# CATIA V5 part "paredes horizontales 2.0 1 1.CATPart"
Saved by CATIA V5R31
Part number: paredes horizontales 2.0
Bounding box of the stored display mesh (mm): x -153.3 to 153.3, y 0 to 3.3, z 0 to 315
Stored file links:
  C:\Users\189361\Desktop\paredes horizontales 2.0 1 1.CATPart
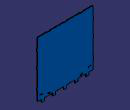
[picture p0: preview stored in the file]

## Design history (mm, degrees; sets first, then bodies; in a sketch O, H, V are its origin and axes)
Body1 (main body)
  Sketch1 on zx-plane, origin (0, 0, 0), H (-1, 0, 0), V (0, 0, 1)
    point P1 (-127.65, 15)
    line L1 (-127.65, 15) -> (-150, 15)
    point P2 (-150, 15)
    line L2 (-150, 15) -> (-150, 65)
    point P3 (-150, 65)
    line L3 (-150, 65) -> (-153.3, 65)
    point P4 (-153.3, 65)
    line L4 (-153.3, 65) -> (-153.3, 80)
    point P5 (-153.3, 80)
    line L5 (-153.3, 80) -> (-150, 80)
    point P6 (-150, 80)
    line L6 (-150, 80) -> (-150, 165)
    point P7 (-150, 165)
    line L7 (-150, 165) -> (-153.3, 165)
    point P8 (-153.3, 165)
    line L8 (-153.3, 165) -> (-153.3, 180)
    point P9 (-153.3, 180)
    line L9 (-153.3, 180) -> (-150, 180)
    point P10 (-150, 180)
    line L10 (-150, 180) -> (-150, 247.5)
    point P11 (-150, 247.5)
    line L11 (-150, 247.5) -> (-153.3, 247.5)
    point P12 (-153.3, 247.5)
    line L12 (-153.3, 247.5) -> (-153.3, 262.5)
    point P13 (-150, 315)
    line L13 (-150, 315) -> (-97.5, 315)
    point P14 (-97.5, 315)
    line L14 (-97.5, 315) -> (-97.5, 311.7)
    point P15 (-97.5, 311.7)
    line L15 (-97.5, 311.7) -> (-82.5, 311.7)
    point P16 (-82.5, 311.7)
    line L16 (-82.5, 311.7) -> (-82.5, 315)
    point P17 (-82.5, 315)
    line L17 (-82.5, 315) -> (-7.5, 315)
    point P18 (-7.5, 315)
    line L18 (-7.5, 315) -> (-7.5, 311.7)
    point P19 (-7.5, 311.7)
    line L19 (-7.5, 311.7) -> (0, 311.7)
    point P20 (0, 311.7)
    line L20 (-127.65, 15) -> (-127.65, 0)
    point P21 (-127.65, 0)
    line L21 (-127.65, 0) -> (-112.35, 0)
    point P22 (-112.35, 0)
    line L22 (-112.35, 0) -> (-112.35, 15)
    point P23 (-112.35, 15)
    line L23 (-112.35, 15) -> (-67.65, 15)
    point P24 (-67.65, 15)
    line L24 (-67.65, 15) -> (-67.65, 0)
    point P25 (-67.65, 0)
    line L25 (-67.65, 0) -> (-52.35, 0)
    point P26 (-52.35, 0)
    line L26 (-52.35, 0) -> (-52.35, 15)
    point P27 (-52.35, 15)
    point P28 (0, 20)
    construction line L27 (-120, 69.0879) -> (-120, 15.3646)
    point P29 (-120, 69.0879)
    point P30 (-120, 15.3646)
    construction line L28 (-60, 77.7749) -> (-60, 37.1309)
    point P31 (-60, 77.7749)
    point P32 (-60, 37.1309)
    construction line L29 (-90, 395.2312) -> (-90, 371.5645)
    point P33 (-90, 395.2312)
    point P34 (-90, 371.5645)
    construction line L30 (-191.266, 72.5) -> (-134.1858, 72.5)
    point P35 (-191.266, 72.5)
    point P36 (-134.1858, 72.5)
    construction line L31 (-191.266, 172.5) -> (-119.3784, 172.5)
    point P37 (-191.266, 172.5)
    point P38 (-119.3784, 172.5)
    point P39 (0, 20)
    point P40 (90, 371.5645)
    line L32 (-52.35, 15) -> (-7.65, 15)
    point P41 (-7.65, 15)
    line L33 (-7.65, 15) -> (-7.65, 0)
    point P42 (-7.65, 0)
    line L34 (-7.65, 0) -> (0, 0)
    point P43 (0, 20)
    point P44 (90, 371.5645)
    point P45 (90, 395.2312)
    construction line L35 (90, 395.2312) -> (90, 371.5645)
    point P46 (0, 20)
    point P47 (-153.3, 262.5)
    line L36 (-153.3, 262.5) -> (-150, 262.5)
    point P48 (-150, 262.5)
    line L37 (-150, 262.5) -> (-150, 315)
    point P49 (-150, 315)
    axis line L38 (-181.0123, 255) -> (-138.6791, 255)
    point P50 (-181.0123, 255)
    point P51 (-138.6791, 255)
    point P52 (0, 0)
    point P53 (127.65, 15)
    point P54 (150, 15)
    point P55 (150, 65)
    point P56 (153.3, 65)
    point P57 (153.3, 80)
    point P58 (150, 80)
    point P59 (150, 165)
    point P60 (153.3, 165)
    point P61 (153.3, 180)
    point P62 (150, 180)
    point P63 (150, 247.5)
    point P64 (153.3, 247.5)
    point P65 (150, 315)
    point P66 (97.5, 315)
    point P67 (97.5, 311.7)
    point P68 (82.5, 311.7)
    point P69 (82.5, 315)
    point P70 (7.5, 315)
    point P71 (7.5, 311.7)
    point P72 (0, 311.7)
    point P73 (127.65, 0)
    point P74 (112.35, 0)
    point P75 (112.35, 15)
    point P76 (67.65, 15)
    point P77 (67.65, 0)
    point P78 (52.35, 0)
    point P79 (52.35, 15)
    point P80 (0, 20)
    point P81 (120, 15.3646)
    point P82 (120, 69.0879)
    construction line L39 (120, 69.0879) -> (120, 15.3646)
    point P83 (60, 37.1309)
    point P84 (60, 77.7749)
    construction line L40 (60, 77.7749) -> (60, 37.1309)
    point P85 (90, 371.5645)
    point P86 (90, 395.2312)
    construction line L41 (90, 395.2312) -> (90, 371.5645)
    point P87 (134.1858, 72.5)
    point P88 (191.266, 72.5)
    construction line L42 (191.266, 72.5) -> (134.1858, 72.5)
    point P89 (119.3784, 172.5)
    point P90 (191.266, 172.5)
    construction line L43 (191.266, 172.5) -> (119.3784, 172.5)
    point P91 (0, 20)
    point P92 (7.65, 15)
    point P93 (7.65, 0)
    point P94 (0, 20)
    point P95 (153.3, 262.5)
    point P96 (150, 262.5)
    point P97 (150, 315)
    point P98 (138.6791, 255)
    point P99 (181.0123, 255)
    construction line L44 (181.0123, 255) -> (138.6791, 255)
    line L45 (127.65, 15) -> (150, 15)
    line L46 (150, 15) -> (150, 65)
    line L47 (150, 65) -> (153.3, 65)
    line L48 (153.3, 65) -> (153.3, 80)
    line L49 (153.3, 80) -> (150, 80)
    line L50 (150, 80) -> (150, 165)
    line L51 (150, 165) -> (153.3, 165)
    line L52 (153.3, 165) -> (153.3, 180)
    line L53 (153.3, 180) -> (150, 180)
    line L54 (150, 180) -> (150, 247.5)
    line L55 (150, 247.5) -> (153.3, 247.5)
    line L56 (153.3, 247.5) -> (153.3, 262.5)
    line L57 (150, 315) -> (97.5, 315)
    line L58 (97.5, 315) -> (97.5, 311.7)
    line L59 (97.5, 311.7) -> (82.5, 311.7)
    line L60 (82.5, 311.7) -> (82.5, 315)
    line L61 (82.5, 315) -> (7.5, 315)
    line L62 (7.5, 315) -> (7.5, 311.7)
    line L63 (7.5, 311.7) -> (0, 311.7)
    line L64 (127.65, 15) -> (127.65, 0)
    line L65 (127.65, 0) -> (112.35, 0)
    line L66 (112.35, 0) -> (112.35, 15)
    line L67 (112.35, 15) -> (67.65, 15)
    line L68 (67.65, 15) -> (67.65, 0)
    line L69 (67.65, 0) -> (52.35, 0)
    line L70 (52.35, 0) -> (52.35, 15)
    line L71 (52.35, 15) -> (7.65, 15)
    line L72 (7.65, 15) -> (7.65, 0)
    line L73 (7.65, 0) -> (0, 0)
    line L74 (153.3, 262.5) -> (150, 262.5)
    line L75 (150, 262.5) -> (150, 315)
    length L14 = 3.3
    length L20 = 15
    length L3 = 3.3
    distance V L2 = 150
    distance L27 L2 = 30
    length L21 = 15.3
    distance L22 L27 = 7.65
    distance L28 L27 = 60
    distance L26 L28 = 7.65
    distance V L18 = 7.5
    distance L29 L16 = 7.5
    length L15 = 15
    distance L29 V = 90
    length L4 = 15
    distance L30 L3 = 7.5
    distance L31 L7 = 7.5
    distance L31 L30 = 100
    length L34 = 7.65
    distance L17 L23 = 300
    distance L1 L30 = 57.5
    length L12 = 15
    distance L38 L11 = 7.5
    distance L38 L13 = 60
    horizontal: L1 H, L3 H, L5 H, L7 H, L9 H, L11 H, L13 H, L15 H, L17 H, L19 H, L21 H, L23 H, L25 H, L30 H, L31 H, L32 H, L34 H, L36 H, L38 H
    vertical: L2 V, L4 V, L6 V, L8 V, L10 V, L12 V, L14 V, L16 V, L18 V, L20 V, L22 V, L24 V, L26 V, L27 V, L28 V, L29 V, L33 V, L37 V
    coincidence: P6 L2, P8 L4, P10 L2, P12 L4, P13 L2, P19 L15, P20 V, P21 H, P23 L1, P25 H, P27 L1, P28 V, P42 H
    equal size: L14 L16, L16 L18, L20 L22, L22 L24, L24 L26, L3 L5, L5 L7, L7 L9, L9 L11, L25 L21, L4 L8, L36 L11
    symmetry: P28 P39 V, P34 P40 V, P28 P43 V, P34 P44 V, P33 P45 V, L29 L35 V, P39 P46 V, O P52 V, P1 P53 V, P2 P54 V, P3 P55 V, P4 P56 V, P5 P57 V, P6 P58 V, P7 P59 V, P8 P60 V, P9 P61 V, P10 P62 V, P11 P63 V, P12 P64 V, P13 P65 V, P14 P66 V, P15 P67 V, P16 P68 V, P17 P69 V, P18 P70 V, P19 P71 V, P20 P72 V, P21 P73 V, P22 P74 V, P23 P75 V, P24 P76 V, P25 P77 V, P26 P78 V, P27 P79 V, P28 P80 V, P30 P81 V, P29 P82 V, L27 L39 V, P32 P83 V, P31 P84 V, L28 L40 V, P34 P85 V, P33 P86 V, L29 L41 V, P36 P87 V, P35 P88 V, L30 L42 V, P38 P89 V, P37 P90 V, L31 L43 V, P39 P91 V, P41 P92 V, P42 P93 V, P43 P94 V, P47 P95 V, P48 P96 V, P49 P97 V, P51 P98 V, P50 P99 V, L38 L44 V, L1 L45 V, L2 L46 V, L3 L47 V, L4 L48 V, L5 L49 V, L6 L50 V, L7 L51 V, L8 L52 V, L9 L53 V, L10 L54 V, L11 L55 V, L12 L56 V, L13 L57 V, L14 L58 V, L15 L59 V, L16 L60 V, L17 L61 V, L18 L62 V, L19 L63 V, L20 L64 V, L21 L65 V, L22 L66 V, L23 L67 V, L24 L68 V, L25 L69 V, L26 L70 V, L32 L71 V, L33 L72 V, L34 L73 V, L36 L74 V, L37 L75 V
  Pad1: profile Sketch1, direction (0, 1, 0), length 3.3
  Sketch2 on end face of Pad1, origin (0, 3.3, 0), H (-1, 0, 0), V (0, 0, 1)
    construction line L1 (0, 15) -> (-71.5, 15)
    point P1 (0, 15)
    point P2 (-71.5, 15)
    point P3 (-148, 44.8437)
    construction line L2 (-148, 44.8437) -> (-71.5, 17)
    point P4 (-71.5, 17)
    construction line L3 (-71.5, 17) -> (-70.3713, 20.101)
    point P5 (-70.3713, 20.101)
    construction line L4 (-70.3713, 20.101) -> (-146.8713, 47.9447)
    point P6 (-146.8713, 47.9447)
    construction line L5 (-146.8713, 47.9447) -> (-148, 44.8437)
    line L6 (-137.4744, 44.5245) -> (-123.379, 39.3942)
    line L7 (-123.379, 39.3942) -> (-124.5077, 36.2932)
    line L8 (-124.5077, 36.2932) -> (-138.6031, 41.4235)
    line L9 (-138.6031, 41.4235) -> (-137.4744, 44.5245)
    point P7 (-137.4744, 44.5245)
    point P8 (-123.379, 39.3942)
    point P9 (-124.5077, 36.2932)
    point P10 (-138.6031, 41.4235)
    construction line L10 (-71.5, 15) -> (-71.5, 17)
    point P11 (-71.5, 17)
    axis line L11 (-150, 44.8437) -> (-148, 44.8437)
    point P12 (-150, 44.8437)
    point P13 (-148, 44.8437)
    reference projected line E1 (-150, 165) -> (-150, 80) from edge [face of Pad1 from Sketch1.L6 | end face of Pad1]
    reference projected line E2 (-52.35, 15) -> (-7.65, 15) from edge [face of Pad1 from Sketch1.L32 | end face of Pad1]
    line L12 (-93.8636, 28.6515) -> (-79.7683, 23.5212)
    line L13 (-79.7683, 23.5212) -> (-80.8969, 20.4202)
    line L14 (-80.8969, 20.4202) -> (-94.9923, 25.5505)
    line L15 (-94.9923, 25.5505) -> (-93.8636, 28.6515)
    point P14 (-93.8636, 28.6515)
    point P15 (-79.7683, 23.5212)
    point P16 (-80.8969, 20.4202)
    point P17 (-94.9923, 25.5505)
    point P18 (71.5, 15)
    point P19 (148, 44.8437)
    point P20 (71.5, 17)
    construction line L16 (148, 44.8437) -> (71.5, 17)
    point P21 (70.3713, 20.101)
    construction line L17 (71.5, 17) -> (70.3713, 20.101)
    point P22 (146.8713, 47.9447)
    construction line L18 (70.3713, 20.101) -> (146.8713, 47.9447)
    construction line L19 (146.8713, 47.9447) -> (148, 44.8437)
    point P23 (137.4744, 44.5245)
    point P24 (123.379, 39.3942)
    point P25 (124.5077, 36.2932)
    point P26 (138.6031, 41.4235)
    point P27 (71.5, 17)
    construction line L20 (71.5, 15) -> (71.5, 17)
    point P28 (148, 44.8437)
    point P29 (150, 44.8437)
    construction line L21 (150, 44.8437) -> (148, 44.8437)
    point P30 (93.8636, 28.6515)
    point P31 (79.7683, 23.5212)
    point P32 (80.8969, 20.4202)
    point P33 (94.9923, 25.5505)
    line L22 (137.4744, 44.5245) -> (123.379, 39.3942)
    line L23 (123.379, 39.3942) -> (124.5077, 36.2932)
    line L24 (124.5077, 36.2932) -> (138.6031, 41.4235)
    line L25 (138.6031, 41.4235) -> (137.4744, 44.5245)
    line L26 (93.8636, 28.6515) -> (79.7683, 23.5212)
    line L27 (79.7683, 23.5212) -> (80.8969, 20.4202)
    line L28 (80.8969, 20.4202) -> (94.9923, 25.5505)
    line L29 (94.9923, 25.5505) -> (93.8636, 28.6515)
    length L1 = 71.5
    length L5 = 3.3
    length L10 = 2
    length L11 = 2
    length L9 = 3.3
    length L6 = 15
    length L12 = 15
    angle L14 L1 = 160
    length L15 = 3.3
    distance L3 L13 = 10
    length L2 = 81.4096 (reference)
    distance L9 L5 = 10
    coincidence: P1 V, P4 P11, P12 E1, P3 P13, L1 E2, L12 L4, L6 L4
    horizontal: L1 H, L11 H
    perpendicularity: L3 L2, L5 L2, L7 L6, L9 L6, L13 L12, L15 L12
    parallelism: L4 L2, L8 L6, L14 L12
    vertical: L10 V
    symmetry: P2 P18 V, P3 P19 V, P4 P20 V, L2 L16 V, P5 P21 V, L3 L17 V, P6 P22 V, L4 L18 V, L5 L19 V, P7 P23 V, P8 P24 V, P9 P25 V, P10 P26 V, P11 P27 V, L10 L20 V, P13 P28 V, P12 P29 V, L11 L21 V, P14 P30 V, P15 P31 V, P16 P32 V, P17 P33 V, L6 L22 V, L7 L23 V, L8 L24 V, L9 L25 V, L12 L26 V, L13 L27 V, L14 L28 V, L15 L29 V
  Pocket1: profile Sketch2, direction (0, -1, 0), length 3.3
